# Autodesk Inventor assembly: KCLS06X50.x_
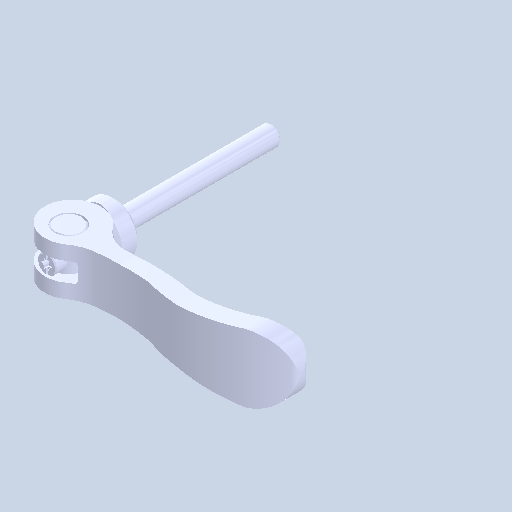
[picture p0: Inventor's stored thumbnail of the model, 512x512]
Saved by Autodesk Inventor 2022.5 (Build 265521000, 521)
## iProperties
Created: 2024-08
Part Number: KCLS06X50.x_
Document SubType Name: Assembly
Designer: ImaoCorp
Author: ImaoCorp
Sending System: SOLIDWORKS 2022-2022290
MC: AMD64
MC_MODEL: Intel64 Family 6 Model 60 Stepping 3, GenuineIntel
OS: Windows_NT
FRU: Parasolid Version 33.1, build 260,  4-25-2022
FORMAT: text
GUISE: transmit
KEY: FILEKCLS06X50.x_t
DATE: Thu Aug 29 10:55:00 2024
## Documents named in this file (5)
- Y:\5.更新分\2024年対応\1001_KCL\データ\kcls06x50\KCLS06X50.x_.iam
- Y:\5.更新分\2024年対応\1001_KCL\データ\kcls06x50\KCLS06X50_01.ipt
- Y:\5.更新分\2024年対応\1001_KCL\データ\kcls06x50\KCLS06X50_02.ipt
- Y:\5.更新分\2024年対応\1001_KCL\データ\kcls06x50\KCLS06X50_03.ipt
- Y:\5.更新分\2024年対応\1001_KCL\データ\kcls06x50\KCLS06X50_04.ipt
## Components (4 placed, 4 different names)
1. KCLS06X50_01
2. KCLS06X50_02
3. KCLS06X50_03
4. KCLS06X50_04
